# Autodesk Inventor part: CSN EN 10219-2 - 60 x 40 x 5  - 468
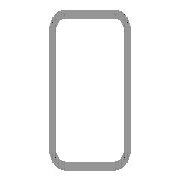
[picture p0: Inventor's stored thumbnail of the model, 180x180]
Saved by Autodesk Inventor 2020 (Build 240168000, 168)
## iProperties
Created: 2019-01
Part Number: CSN EN 10219-2 - 60 x 40 x 5  - 468
Material: Ocel, měkká
Description: Duté svařované profily tvářené za studena z nelegované a jemnozrnné konstrukční oceli
Document SubType Name: Modeling
Standard: CSN EN 10219-2
Designer: doma
Standards Organization: CSN
Language: cs-CZ
Size Designation: 60 x 40 x 5  - 468
Categories: <MemberInstance><Categories><Category DisplayName="Konstrukční profily" InternalName="089c4875-fa83-4c05-b084-43b9cc11f5ed" Mnemonic="GRDR"><CategoryParameter D
Stock Number: 60 x 40 x 5
Density: 7.85 g/cm^3
Appearance: Pololeštěná
Mass: 3069.9 g
Surface Area: 1580.99 cm^2
Volume: 391.07 cm^3
IsCustomPart: 1
G_L: 468,000 mm
Author: doma
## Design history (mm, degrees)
node "Počáteční rovina"
node "Koncová rovina"
sketch "Náčrt"
  geometry: L1 (-20, -20)-(-20, 20); L2 (-10, 30)-(10, 30); L3 (20, 20)-(20, -20); L4 (10, -30)-(-10, -30); L5 (-10, 25)-(10, 25); L6 (15, 20)-(15, -20); L7 (10, -25)-(-10, -25); L8 (-15, -20)-(-15, 20); L9 (0, 37.102)-(0, -37.102) reference; L10 (-23.102, 0)-(23.102, 0) reference; A1 r 10 centre (-10, -20) between (-20, -20) and (-10, -30); A2 r 10 centre (-10, 20) between (-10, 30) and (-20, 20); A3 r 10 centre (10, 20) between (20, 20) and (10, 30); A4 r 10 centre (10, -20) between (10, -30) and (20, -20); A5 r 5 centre (-10, 20) between (-10, 25) and (-15, 20); A6 r 5 centre (10, 20) between (15, 20) and (10, 25); A7 r 5 centre (10, -20) between (10, -25) and (15, -20); A8 r 5 centre (-10, -20) between (-15, -20) and (-10, -25)
  constraints: 16 end point, 16 point on circle, 8 centre point, 8 tangent, 4 parallel, 3 equal radius, 2 perpendicular, 7 other
  dimensions: "d7" = 10 radius of A1 (= G_IR); "d10" = 60 distance between parallel lines of L2 L4 (= G_H); "d11" = 40 distance between parallel lines of L1 L3 (= G_W); "d12" = 5 distance between parallel lines of L3 L6 (= G_T); "d15" = 30 distance between parallel lines of L2 L10 (= 0.5 x d10); "d16" = 20 distance between parallel lines of L9 L3 (= 0.5 x d11)
extrude "Těleso" new body sketch "Náčrt" stored distance "d3" = 468 (= G_L); taper "d4" = 0 deg
node "Driven Length"
  sketch "Sketch3"
    geometry: L1 (0, 0)-(10, 0) reference
    constraints: 2 end point, 1 horizontal
  workplane "Work Plane3"
  sketch "Sketch4"
    geometry: L1 (-2, 0)-(12, 0) reference; L2 (-2, 468)-(12, 468) reference
    dimensions: "d18" = 468 distance between parallel lines of L1 L2 (derived)
body "Solid1"
other parameters: "G_W" = 40 [user parameter; used in 1 equation term], "G_H" = 60 [user parameter; used in 1 equation term], "G_T" = 5 [user parameter; used in 1 equation term], "G_IR" = 10 [user parameter; used in 1 equation term], "G_L" = 468 (= d18) [user parameter; used in 1 equation term], "G_OFFSET_START" = 0 [user parameter; used in 1 equation term], "G_OFFSET_END" = 0 [user parameter; used in 1 equation term], "d13" = 0 (computed from G_OFFSET_START), "d14" = 468 (= G_OFFSET_END + B_L), "B_L" = 468 [user parameter; used in 1 equation term], "d17" = 90 deg
